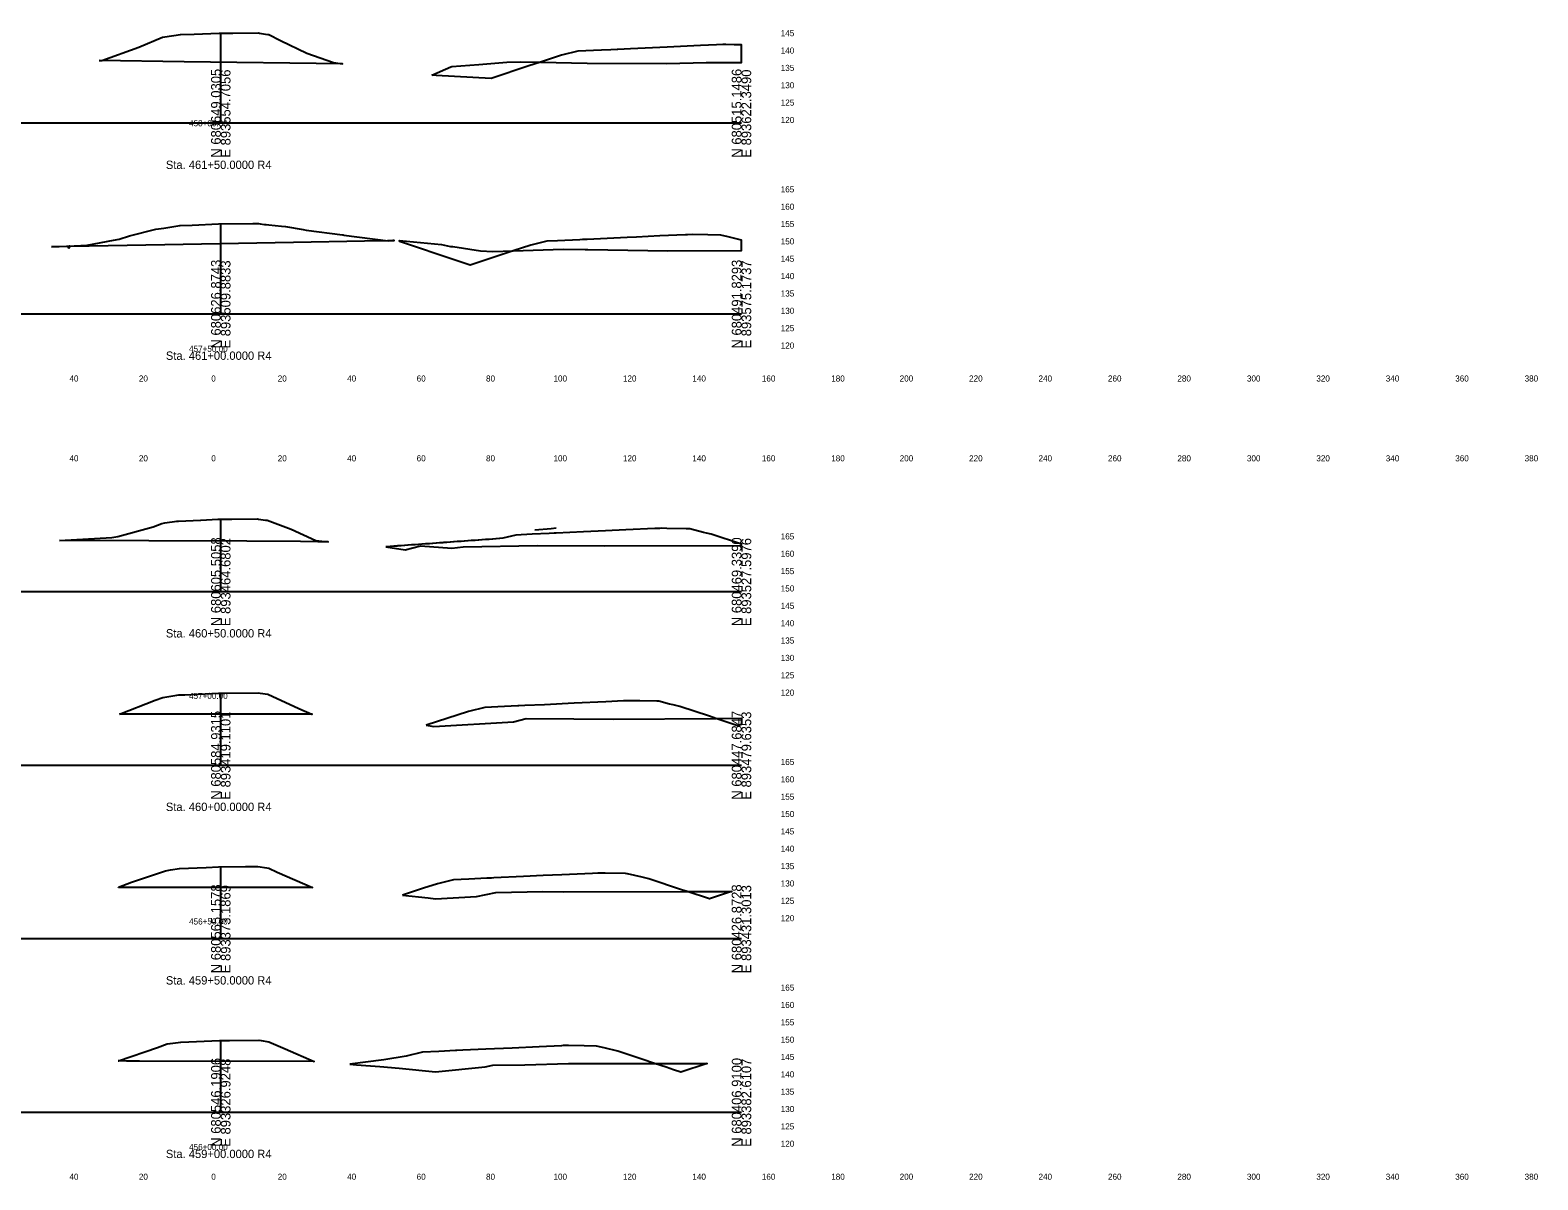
# Model space of a CAD drawing. Extents: x 21059 to 22955, y 6470 to 17494.
# Drawn here: x 21589.9 to 22024.2, y 7855.3 to 8186.6 of the extents above; entities that cross this region are included whole.
import ezdxf

# ---------------------------------------------------------------- set-up
doc = ezdxf.new("R2010")
doc.units = 0
for name, color, linetype in [('CONST_DCH', 7, 'Continuous'), ('Draft_XS_Grid', 7, 'Continuous'), ('Draft_XS_Text', 7, 'Continuous'), ('DTM CONTOURS_MAJOR', 7, 'Continuous'), ('SLOPE_STAKES_FILL', 7, 'Continuous'), ('X_PROFILES_1', 7, 'Continuous'), ('XS_P_DRAINAGE', 7, 'Continuous'), ('XS_P_TX_CLEARZONE', 7, 'Continuous'), ('XS_SHEET_EW_TX_VOLUME', 7, 'Continuous')]:
    doc.layers.add(name, color=color, linetype=linetype)

msp = doc.modelspace()

# ---------------------------------------------------------------- linework, layer by layer
at = {"layer": 'DTM CONTOURS_MAJOR'}
for p, q in [((21644.84, 8159.84), (21644.84, 8185.77)), ((21494.84, 8159.84), (21644.84, 8159.84)), ((21644.84, 8159.84), (21794.84, 8159.84)), ((21644.84, 8104.84), (21644.84, 8130.84)), ((21494.84, 8104.84), (21644.84, 8104.84)), ((21644.84, 8104.84), (21794.84, 8104.84)), ((21644.84, 8024.84), (21644.84, 8045.73)), ((21494.84, 8024.84), (21644.84, 8024.84)), ((21644.84, 8024.84), (21794.84, 8024.84)), ((21644.84, 7974.84), (21644.84, 7995.64)), ((21494.84, 7974.84), (21644.84, 7974.84)), ((21644.84, 7974.84), (21794.84, 7974.84)), ((21644.84, 7924.84), (21644.84, 7945.59)), ((21494.84, 7924.84), (21644.84, 7924.84)), ((21644.84, 7924.84), (21794.84, 7924.84)), ((21644.84, 7874.84), (21644.84, 7895.58)), ((21494.84, 7874.84), (21644.84, 7874.84)), ((21644.84, 7874.84), (21794.84, 7874.84))]:
    msp.add_line(p, q, dxfattribs=at)
at = {"layer": 'XS_P_DRAINAGE'}
for points in [[(21601.1, 8123.73), (21601, 8123.72)], [(21601.25, 8124.21), (21601.1, 8123.73)]]:
    msp.add_lwpolyline(points, dxfattribs=at)
at = {"layer": 'XS_P_TX_CLEARZONE'}
msp.add_lwpolyline([(21735.27, 8042.63), (21740.02, 8043.02), (21741.42, 8043.14)], dxfattribs=at)
at = {"layer": 'XS_SHEET_EW_TX_VOLUME'}
for points in [[(21609.85, 8177.83), (21610.53, 8177.87), (21621.2, 8181.69), (21628.07, 8184.6), (21631.31, 8185.05), (21633.26, 8185.34), (21637.15, 8185.45), (21644.35, 8185.75), (21648.28, 8185.72), (21655.75, 8185.77), (21655.95, 8185.71), (21657.7, 8185.43), (21658.41, 8185.37), (21658.66, 8185.36), (21658.68, 8185.37), (21662.09, 8183.58), (21669.59, 8179.99), (21677.3, 8177.3), (21679.89, 8176.87), (21634.26, 8177.5)], [(21736.92, 8177.35), (21750.34, 8177.06), (21773.38, 8176.99), (21784.67, 8177.28), (21794.84, 8177.25), (21794.84, 8182.33), (21792.76, 8182.38), (21790.33, 8182.43), (21789.68, 8182.45), (21789.46, 8182.44), (21787.65, 8182.35), (21783.06, 8182.14), (21773.45, 8181.69), (21762.87, 8181.2), (21759.25, 8181.03), (21758.98, 8181.02), (21757.22, 8180.94), (21754.5, 8180.81), (21747.66, 8180.49), (21743.02, 8179.35)], [(21705.66, 8173.61), (21711.12, 8176.06), (21711.4, 8176.13), (21719.17, 8176.69), (21727.22, 8177.33), (21731.08, 8177.48), (21736.92, 8177.35), (21733.57, 8176.26), (21722.72, 8172.7), (21706.9, 8173.55)], [(21596.08, 8124.16), (21602.64, 8124.47), (21606.38, 8124.59), (21613.95, 8126.05), (21615.54, 8126.38), (21618.53, 8127.32), (21626.13, 8129.22), (21628.44, 8129.5), (21633.08, 8130.28), (21633.14, 8130.28), (21636.6, 8130.43), (21644.19, 8130.75), (21654.11, 8130.83), (21655.67, 8130.84), (21656.14, 8130.75), (21657.41, 8130.62), (21657.89, 8130.56), (21658.67, 8130.51), (21662.32, 8130.13), (21663.52, 8130.01), (21668.57, 8129.15), (21669.48, 8128.92), (21679.95, 8127.6), (21680.18, 8127.57), (21680.26, 8127.56), (21693.06, 8125.92), (21694.83, 8125.95), (21694.44, 8125.94), (21692.87, 8125.91), (21686.23, 8125.79), (21665.83, 8125.42), (21628.74, 8124.75)], [(21696.35, 8125.71), (21696.35, 8125.95), (21708.45, 8124.78), (21710.97, 8124.23), (21711.69, 8124.22), (21719.69, 8123.03), (21723.24, 8122.8), (21729.08, 8122.98), (21716.64, 8118.91), (21712.98, 8120.14)], [(21729.08, 8122.98), (21743.5, 8123.45), (21749.81, 8123.38), (21750.58, 8123.34), (21773.64, 8122.98), (21794.84, 8123.13), (21794.84, 8126.05), (21790.97, 8127.01), (21788.86, 8127.53), (21785.13, 8127.62), (21780.78, 8127.71), (21779.29, 8127.65), (21778.75, 8127.62), (21771.35, 8127.28), (21764.55, 8126.96), (21761.95, 8126.84), (21750.34, 8126.3), (21749.04, 8126.24), (21748.31, 8126.21), (21741.87, 8125.91), (21738.75, 8125.77), (21734.11, 8124.63)], [(21601, 8123.72), (21601, 8124.39), (21601.25, 8124.4), (21601.25, 8124.21), (21601.1, 8123.73)], [(21598.36, 8039.57), (21613.44, 8040.44), (21615.17, 8040.71), (21625.36, 8043.5), (21627.83, 8044.45), (21628.76, 8044.61), (21632.22, 8045.14), (21632.67, 8045.13), (21639.02, 8045.43), (21639.06, 8045.43), (21643.99, 8045.64), (21648.07, 8045.67), (21655.45, 8045.73), (21655.75, 8045.68), (21657.73, 8045.42), (21658.24, 8045.37), (21665.16, 8042.78), (21672.22, 8039.56), (21675.77, 8039.18), (21672.79, 8039.19), (21667.78, 8039.22), (21652.33, 8039.3), (21624.11, 8039.44)], [(21692.39, 8037.7), (21697.98, 8036.81), (21702.37, 8038.04), (21711.38, 8037.37), (21714.64, 8037.75), (21736.1, 8038.1), (21755.52, 8037.99), (21794.84, 8038.1), (21794.84, 8038.45), (21786.06, 8041.34), (21784.78, 8041.66), (21783.9, 8041.88), (21779.94, 8042.86), (21779.71, 8042.86), (21778.94, 8042.88), (21773.36, 8043.01), (21771.86, 8043.04), (21771.34, 8043.02), (21769.83, 8042.95), (21761.49, 8042.56), (21755.62, 8042.29), (21749.28, 8042), (21741.42, 8041.64), (21740.83, 8041.61), (21739.39, 8041.54), (21734.56, 8041.32), (21729.82, 8041.1), (21726.06, 8040.18), (21725.21, 8040.09), (21725.11, 8040.08), (21724.2, 8040.02), (21724.09, 8040.01), (21723.18, 8039.94), (21723.08, 8039.93), (21722.17, 8039.87), (21722.06, 8039.86), (21721.16, 8039.79), (21721.05, 8039.79), (21720.14, 8039.72), (21720.04, 8039.71), (21719.13, 8039.65), (21719.02, 8039.64), (21718.11, 8039.57), (21718.01, 8039.57), (21717.1, 8039.5), (21716.99, 8039.49), (21716.08, 8039.43), (21715.98, 8039.42), (21715.07, 8039.35), (21714.97, 8039.34), (21714.06, 8039.28), (21713.95, 8039.27), (21713.04, 8039.2), (21712.94, 8039.2), (21712.03, 8039.13), (21711.92, 8039.12), (21711.01, 8039.06), (21710.91, 8039.05), (21710, 8038.98), (21709.89, 8038.98), (21708.99, 8038.91), (21708.88, 8038.9), (21707.97, 8038.84), (21707.87, 8038.83), (21706.96, 8038.76), (21706.85, 8038.75), (21705.94, 8038.69), (21705.84, 8038.68), (21704.93, 8038.61), (21704.82, 8038.61), (21703.91, 8038.54), (21703.81, 8038.53), (21702.9, 8038.47), (21702.8, 8038.46), (21701.89, 8038.39), (21701.78, 8038.38), (21700.87, 8038.32), (21700.77, 8038.31), (21699.86, 8038.24), (21699.75, 8038.24), (21698.84, 8038.17), (21698.74, 8038.16), (21697.83, 8038.1), (21697.72, 8038.09), (21696.82, 8038.02), (21696.71, 8038.02), (21695.8, 8037.95), (21695.7, 8037.94), (21694.79, 8037.88), (21694.68, 8037.87), (21693.77, 8037.8), (21693.67, 8037.79), (21692.76, 8037.73), (21692.65, 8037.72)], [(21615.7, 7989.54), (21625.92, 7993.5), (21628.17, 7994.27), (21632.2, 7994.95), (21632.78, 7995.03), (21634.52, 7995.1), (21644.2, 7995.55), (21646, 7995.56), (21655.62, 7995.64), (21656.21, 7995.55), (21658.39, 7995.22), (21667.32, 7991.14), (21671.08, 7989.48), (21671.12, 7989.48), (21669.94, 7989.48), (21667.85, 7989.48), (21653.86, 7989.5), (21650.43, 7989.5), (21639.83, 7989.51), (21620.37, 7989.53)], [(21703.96, 7986.29), (21706.18, 7985.93), (21729.17, 7987.24), (21732.79, 7988.22), (21746.59, 7988.14), (21757.94, 7988.1), (21787.4, 7988.29), (21785.63, 7988.88), (21777.12, 7991.68), (21775.2, 7992.16), (21774.14, 7992.42), (21771, 7993.2), (21770.81, 7993.2), (21770.45, 7993.21), (21765.59, 7993.32), (21762.92, 7993.38), (21761.71, 7993.32), (21760.89, 7993.29), (21755.79, 7993.05), (21746.68, 7992.63), (21738.09, 7992.23), (21732.47, 7991.97), (21730.73, 7991.89), (21730.44, 7991.88), (21726.56, 7991.7), (21720.87, 7991.44), (21716.23, 7990.3)], [(21787.4, 7988.29), (21794.84, 7988.34), (21794.84, 7986.5), (21793.83, 7986.17)], [(21615.34, 7939.59), (21615.38, 7939.6), (21619.17, 7941.06), (21628.87, 7944.4), (21630.37, 7944.65), (21632.96, 7945.02), (21640.65, 7945.32), (21644.22, 7945.49), (21652, 7945.56), (21655.54, 7945.59), (21658.07, 7945.21), (21658.66, 7945.12), (21661.11, 7944), (21671.3, 7939.51), (21646.4, 7939.55), (21644.89, 7939.55), (21643.74, 7939.55), (21636.05, 7939.56), (21634.16, 7939.56), (21628.3, 7939.57), (21617.5, 7939.59)], [(21697.23, 7937.35), (21704.59, 7936.6), (21706.69, 7936.27), (21718.5, 7936.94), (21724.09, 7938.15), (21737.62, 7938.43), (21743.56, 7938.32), (21779.21, 7938.37), (21777.59, 7938.91), (21768.16, 7942.02), (21767.01, 7942.3), (21766.2, 7942.5), (21762.04, 7943.53), (21761.91, 7943.53), (21761.41, 7943.55), (21755.55, 7943.68), (21753.96, 7943.72), (21753.41, 7943.69), (21751.93, 7943.62), (21743.08, 7943.21), (21737.72, 7942.96), (21732.02, 7942.7), (21723.51, 7942.31), (21722.87, 7942.28), (21721.48, 7942.21), (21716.26, 7941.97), (21711.91, 7941.77), (21707.26, 7940.63), (21703.21, 7939.31)], [(21779.21, 7938.37), (21792.1, 7938.39), (21791.41, 7938.17), (21785.62, 7936.26)], [(21615.31, 7889.56), (21615.37, 7889.56), (21626.58, 7893.42), (21629.44, 7894.47), (21630.29, 7894.59), (21633.29, 7895.01), (21635.61, 7895.1), (21644.44, 7895.45), (21647.31, 7895.46), (21655.77, 7895.54), (21655.86, 7895.55), (21656.5, 7895.45), (21658.73, 7895.1), (21663.38, 7893.11), (21671.72, 7889.44), (21621.43, 7889.54), (21621.12, 7889.55), (21620.89, 7889.55), (21619.32, 7889.55), (21618.93, 7889.55), (21617.72, 7889.55), (21615.49, 7889.56)], [(21682.04, 7888.63), (21683.97, 7888.48), (21690.67, 7888.02), (21696.25, 7887.51), (21706.74, 7886.44), (21720.97, 7887.9), (21723.23, 7888.39), (21732.42, 7888.47), (21745.02, 7888.86), (21745.54, 7888.87), (21746.24, 7888.87), (21747.59, 7888.87), (21769.79, 7888.86), (21766.14, 7890.06), (21759.19, 7892.35), (21755.3, 7893.31), (21753.07, 7893.87), (21749.51, 7893.95), (21744.99, 7894.05), (21743.43, 7893.98), (21742.96, 7893.96), (21736.59, 7893.66), (21728.74, 7893.3), (21721.22, 7892.95), (21714.53, 7892.64), (21712.87, 7892.57), (21712.5, 7892.55), (21707.63, 7892.32), (21702.93, 7892.11), (21698.29, 7890.97), (21691.81, 7889.85)], [(21769.79, 7888.86), (21784.99, 7888.85), (21777.39, 7886.35), (21775.25, 7887.06), (21773.11, 7887.77)]]:
    msp.add_lwpolyline(points, close=True, dxfattribs=at)

# ---------------------------------------------------------------- texts
at = {"layer": 'CONST_DCH'}
for p in [(21722.68, 8172.64), (21722.68, 8172.64), (21716.6, 8118.85), (21716.6, 8118.85), (21710.32, 8035.05), (21710.32, 8035.05), (21703.92, 7986.23), (21703.92, 7986.23), (21793.8, 7986.11), (21793.8, 7986.11), (21697.19, 7937.29), (21697.19, 7937.29), (21785.58, 7936.2), (21785.58, 7936.2), (21698.25, 7890.91), (21698.25, 7890.91), (21777.35, 7886.29), (21777.35, 7886.29)]:
    msp.add_text('X', height=0.12, dxfattribs=at).set_placement(p)
at = {"layer": 'Draft_XS_Grid'}
for s, p in [('  145  ', (21804.84, 8184.84)), ('  140  ', (21804.84, 8179.84)), ('  135  ', (21804.84, 8174.84)), ('  130  ', (21804.84, 8169.84)), ('  125  ', (21804.84, 8164.84)), ('  120  ', (21804.84, 8159.84)), ('  165  ', (21804.84, 8139.84)), ('  160  ', (21804.84, 8134.84)), ('  155  ', (21804.84, 8129.84)), ('  150  ', (21804.84, 8124.84)), ('  145  ', (21804.84, 8119.84)), ('  140  ', (21804.84, 8114.84)), ('  135  ', (21804.84, 8109.84)), ('  130  ', (21804.84, 8104.84)), ('  125  ', (21804.84, 8099.84)), ('  120  ', (21804.84, 8094.84)), ('  165  ', (21804.84, 8039.84)), ('  160  ', (21804.84, 8034.84)), ('  155  ', (21804.84, 8029.84)), ('  150  ', (21804.84, 8024.84)), ('  145  ', (21804.84, 8019.84)), ('  140  ', (21804.84, 8014.84)), ('  135  ', (21804.84, 8009.84)), ('  130  ', (21804.84, 8004.84)), ('  125  ', (21804.84, 7999.84)), ('  120  ', (21804.84, 7994.84)), ('  165  ', (21804.84, 7974.84)), ('  160  ', (21804.84, 7969.84)), ('  155  ', (21804.84, 7964.84)), ('  150  ', (21804.84, 7959.84)), ('  145  ', (21804.84, 7954.84)), ('  140  ', (21804.84, 7949.84)), ('  135  ', (21804.84, 7944.84)), ('  130  ', (21804.84, 7939.84)), ('  125  ', (21804.84, 7934.84)), ('  120  ', (21804.84, 7929.84)), ('  165  ', (21804.84, 7909.84)), ('  160  ', (21804.84, 7904.84)), ('  155  ', (21804.84, 7899.84)), ('  150  ', (21804.84, 7894.84)), ('  145  ', (21804.84, 7889.84)), ('  140  ', (21804.84, 7884.84)), ('  135  ', (21804.84, 7879.84)), ('  130  ', (21804.84, 7874.84)), ('  125  ', (21804.84, 7869.84)), ('  120  ', (21804.84, 7864.84))]:
    msp.add_text(s, height=1.75, dxfattribs=at).set_placement(p)
at = {"layer": 'Draft_XS_Text'}
for s, p in [('  40  ', (21599.95, 8085.34)), ('  20  ', (21619.95, 8085.34)), ('  0  ', (21640.81, 8085.34)), ('  0  ', (21640.81, 8085.34)), ('  20  ', (21659.95, 8085.34)), ('  40  ', (21679.95, 8085.34)), ('  60  ', (21699.97, 8085.34)), ('  80  ', (21719.95, 8085.34)), ('  100  ', (21739.39, 8085.34)), ('  120  ', (21759.39, 8085.34)), ('  140  ', (21779.39, 8085.34)), ('  160  ', (21799.4, 8085.34)), ('  180  ', (21819.39, 8085.34)), ('  200  ', (21839.1, 8085.34)), ('  220  ', (21859.1, 8085.34)), ('  240  ', (21879.1, 8085.34)), ('  260  ', (21899.11, 8085.34)), ('  280  ', (21919.1, 8085.34)), ('  300  ', (21939.13, 8085.34)), ('  320  ', (21959.13, 8085.34)), ('  340  ', (21979.13, 8085.34)), ('  360  ', (21999.14, 8085.34)), ('  380  ', (22019.13, 8085.34)), ('  40  ', (21599.95, 8062.34)), ('  20  ', (21619.95, 8062.34)), ('  0  ', (21640.81, 8062.34)), ('  0  ', (21640.81, 8062.34)), ('  20  ', (21659.95, 8062.34)), ('  40  ', (21679.95, 8062.34)), ('  60  ', (21699.97, 8062.34)), ('  80  ', (21719.95, 8062.34)), ('  100  ', (21739.39, 8062.34)), ('  120  ', (21759.39, 8062.34)), ('  140  ', (21779.39, 8062.34)), ('  160  ', (21799.4, 8062.34)), ('  180  ', (21819.39, 8062.34)), ('  200  ', (21839.1, 8062.34)), ('  220  ', (21859.1, 8062.34)), ('  240  ', (21879.1, 8062.34)), ('  260  ', (21899.11, 8062.34)), ('  280  ', (21919.1, 8062.34)), ('  300  ', (21939.13, 8062.34)), ('  320  ', (21959.13, 8062.34)), ('  340  ', (21979.13, 8062.34)), ('  360  ', (21999.14, 8062.34)), ('  380  ', (22019.13, 8062.34)), ('  40  ', (21599.95, 7855.34)), ('  20  ', (21619.95, 7855.34)), ('  0  ', (21640.81, 7855.34)), ('  0  ', (21640.81, 7855.34)), ('  20  ', (21659.95, 7855.34)), ('  40  ', (21679.95, 7855.34)), ('  60  ', (21699.97, 7855.34)), ('  80  ', (21719.95, 7855.34)), ('  100  ', (21739.39, 7855.34)), ('  120  ', (21759.39, 7855.34)), ('  140  ', (21779.39, 7855.34)), ('  160  ', (21799.4, 7855.34)), ('  180  ', (21819.39, 7855.34)), ('  200  ', (21839.1, 7855.34)), ('  220  ', (21859.1, 7855.34)), ('  240  ', (21879.1, 7855.34)), ('  260  ', (21899.11, 7855.34)), ('  280  ', (21919.1, 7855.34)), ('  300  ', (21939.13, 7855.34)), ('  320  ', (21959.13, 7855.34)), ('  340  ', (21979.13, 7855.34)), ('  360  ', (21999.14, 7855.34)), ('  380  ', (22019.13, 7855.34))]:
    msp.add_text(s, height=1.75, dxfattribs=at).set_placement(p)
at = {"layer": 'DTM CONTOURS_MAJOR'}
for s, p in [('N 680649.0305', (21644.84, 8149.84)), ('E 893554.7056', (21647.64, 8149.84)), ('N 680515.1486', (21794.84, 8149.84)), ('E 893622.3490', (21797.64, 8149.84)), ('N 680626.8743', (21644.84, 8094.84)), ('E 893509.8833', (21647.64, 8094.84)), ('N 680491.8293', (21794.84, 8094.84)), ('E 893575.1737', (21797.64, 8094.84)), ('N 680605.5058', (21644.84, 8014.84)), ('E 893464.6802', (21647.64, 8014.84)), ('N 680469.3390', (21794.84, 8014.84)), ('E 893527.5976', (21797.64, 8014.84)), ('N 680584.9315', (21644.84, 7964.84)), ('E 893419.1101', (21647.64, 7964.84)), ('N 680447.6847', (21794.84, 7964.84)), ('E 893479.6353', (21797.64, 7964.84)), ('N 680565.1578', (21644.84, 7914.84)), ('E 893373.1869', (21647.64, 7914.84)), ('N 680426.8728', (21794.84, 7914.84)), ('E 893431.3013', (21797.64, 7914.84)), ('N 680546.1906', (21644.84, 7864.84)), ('E 893326.9248', (21647.64, 7864.84)), ('N 680406.9100', (21794.84, 7864.84)), ('E 893382.6107', (21797.64, 7864.84))]:
    msp.add_text(s, height=2.8, rotation=90, dxfattribs=at).set_placement(p)
at = {"layer": 'SLOPE_STAKES_FILL'}
for s, p in [('  458+00.00  ', (21634.4, 8158.89)), ('  457+50.00  ', (21634.4, 8093.89)), ('  457+00.00  ', (21634.4, 7993.89)), ('  456+50.00  ', (21634.41, 7928.89)), ('  456+00.00  ', (21634.41, 7863.89))]:
    msp.add_text(s, height=1.75, dxfattribs=at).set_placement(p)
at = {"layer": 'X_PROFILES_1'}
for s, p in [('Sta. 461+50.0000 R4', (21629.03, 8146.59)), ('Sta. 461+00.0000 R4', (21629.03, 8091.59)), ('Sta. 460+50.0000 R4', (21629.03, 8011.59)), ('Sta. 460+00.0000 R4', (21629.03, 7961.59)), ('Sta. 459+50.0000 R4', (21629.03, 7911.59)), ('Sta. 459+00.0000 R4', (21629.03, 7861.59))]:
    msp.add_text(s, height=2.4, dxfattribs=at).set_placement(p)

doc.saveas('drawing.dxf')
